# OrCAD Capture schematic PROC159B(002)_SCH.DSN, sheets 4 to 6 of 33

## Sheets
4 08. POWER INPUT: size C; title: USB-C POWER
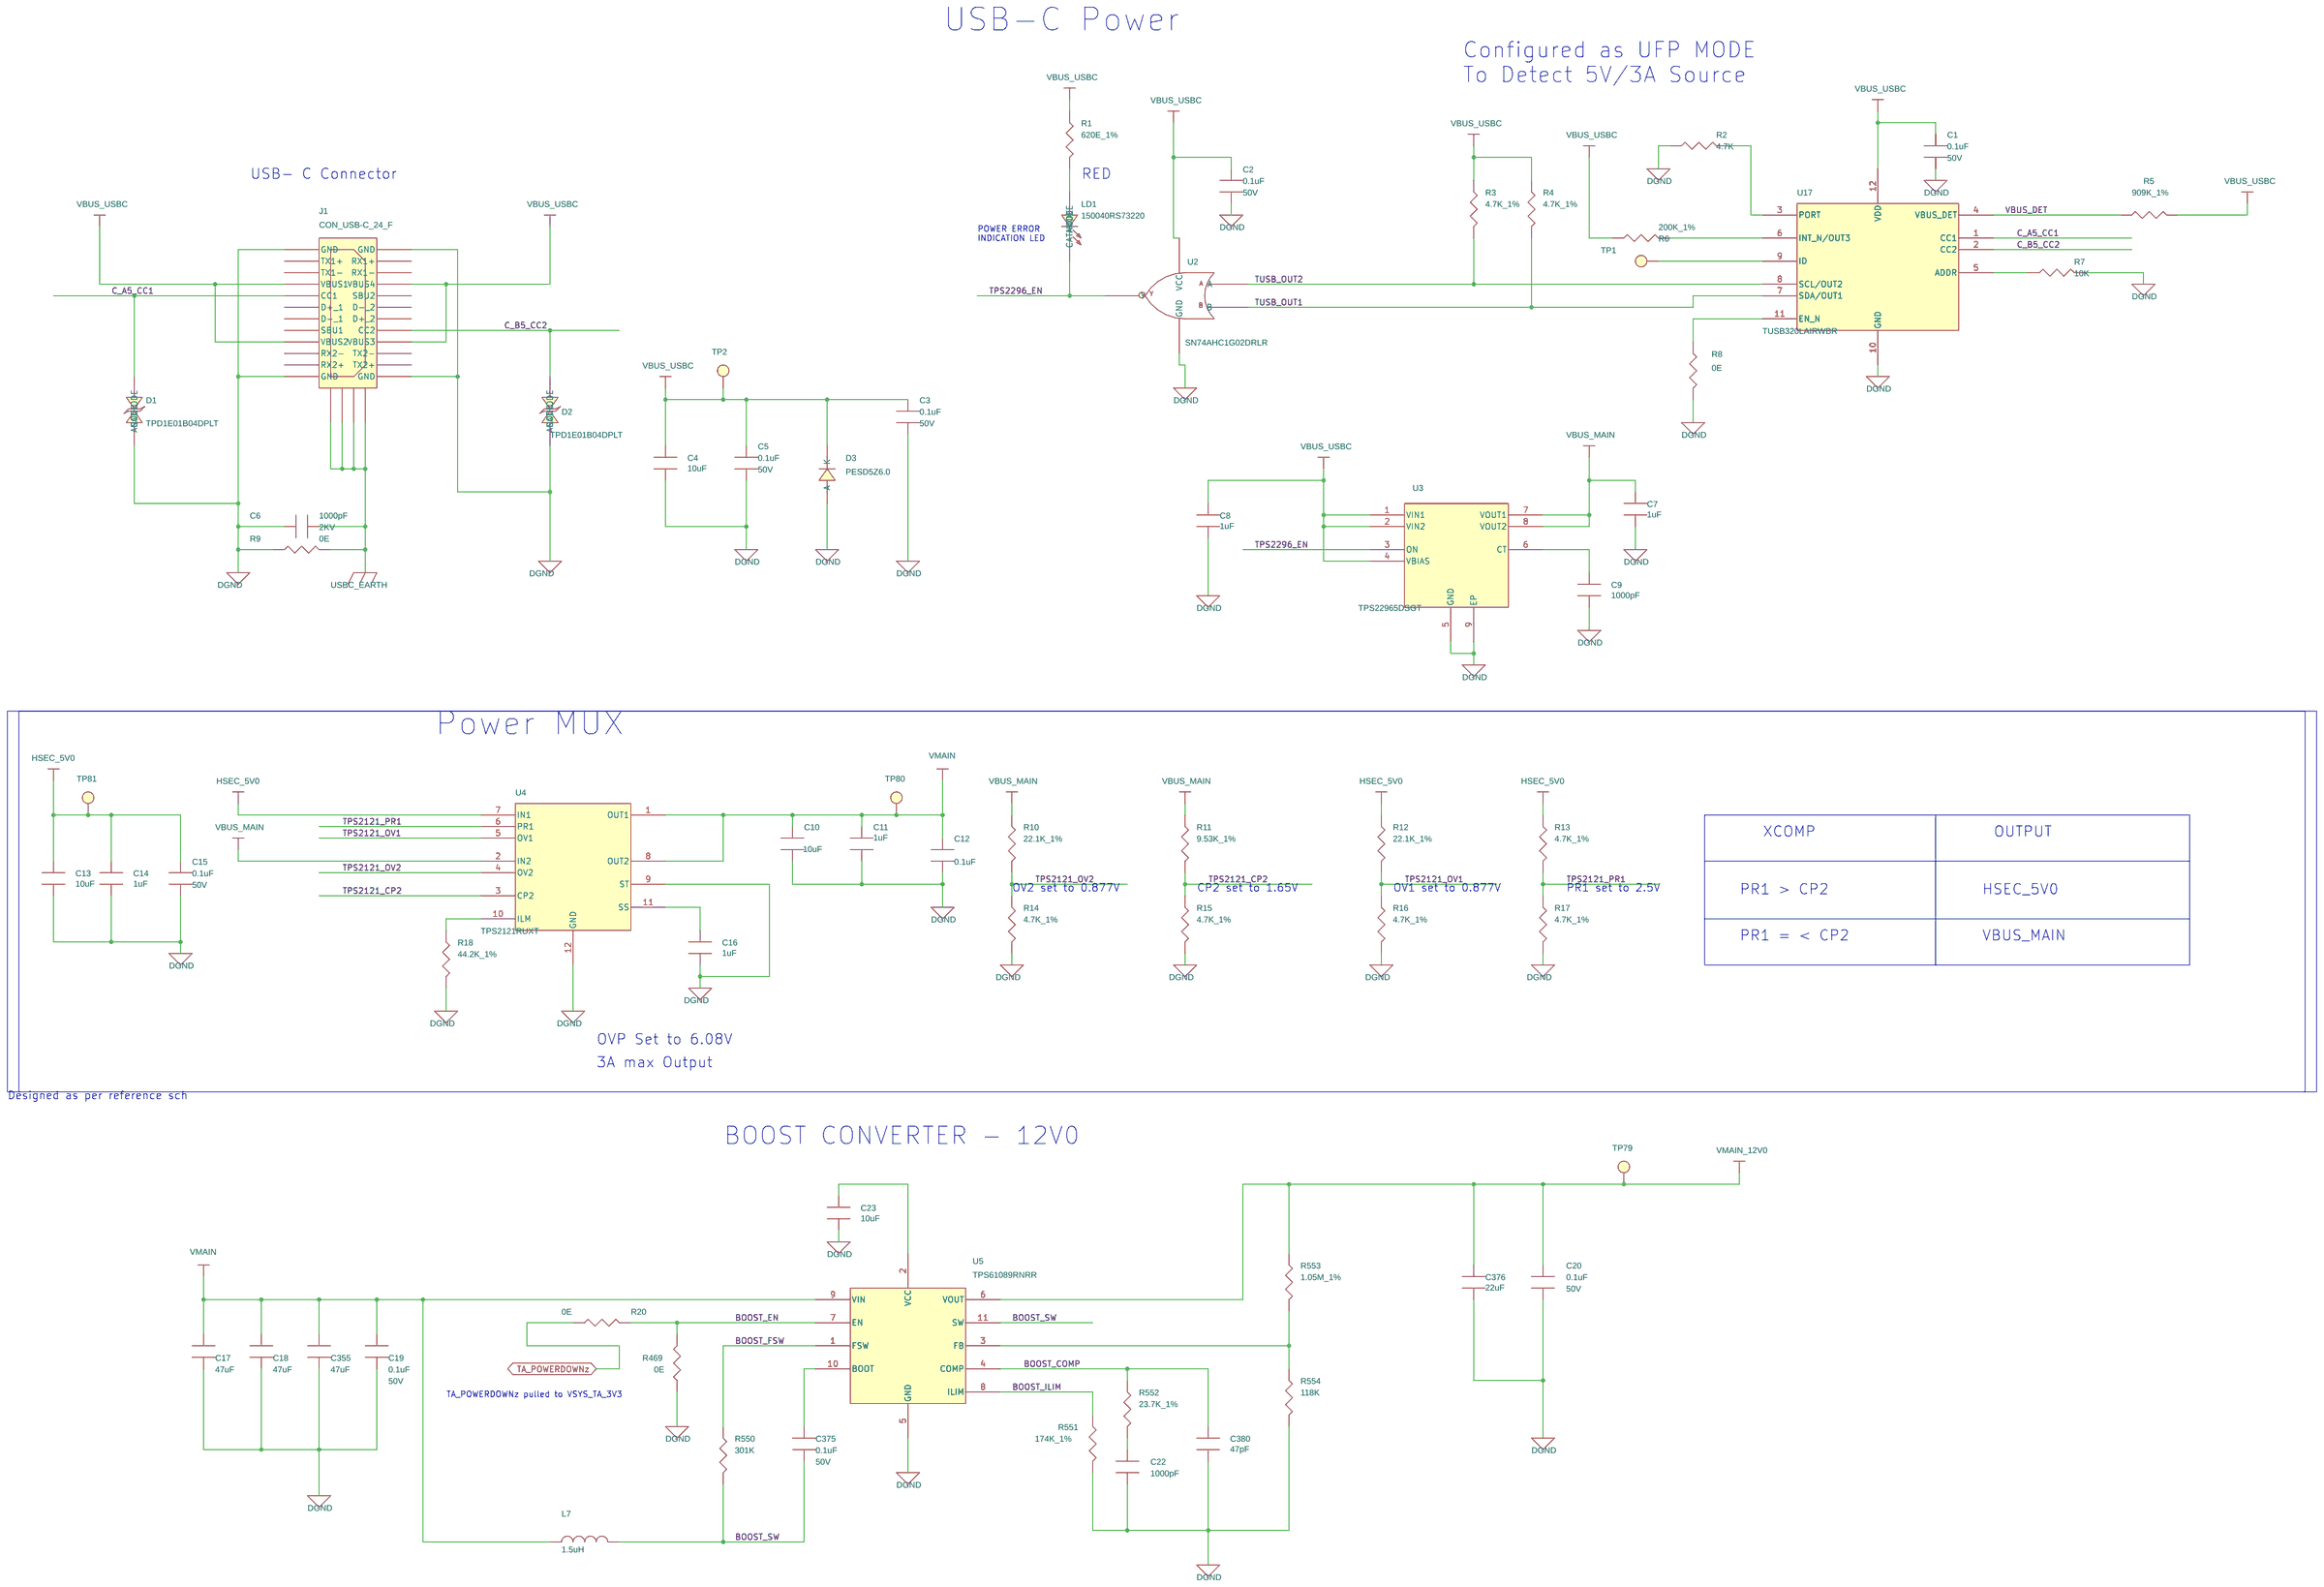
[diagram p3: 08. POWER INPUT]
5 04. POWER SEQUENCE: title: POWER SEQUENCE
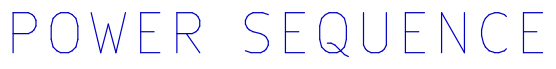
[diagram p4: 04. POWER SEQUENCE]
6 31. HSEC Connector: size C; title: HSEC CONN
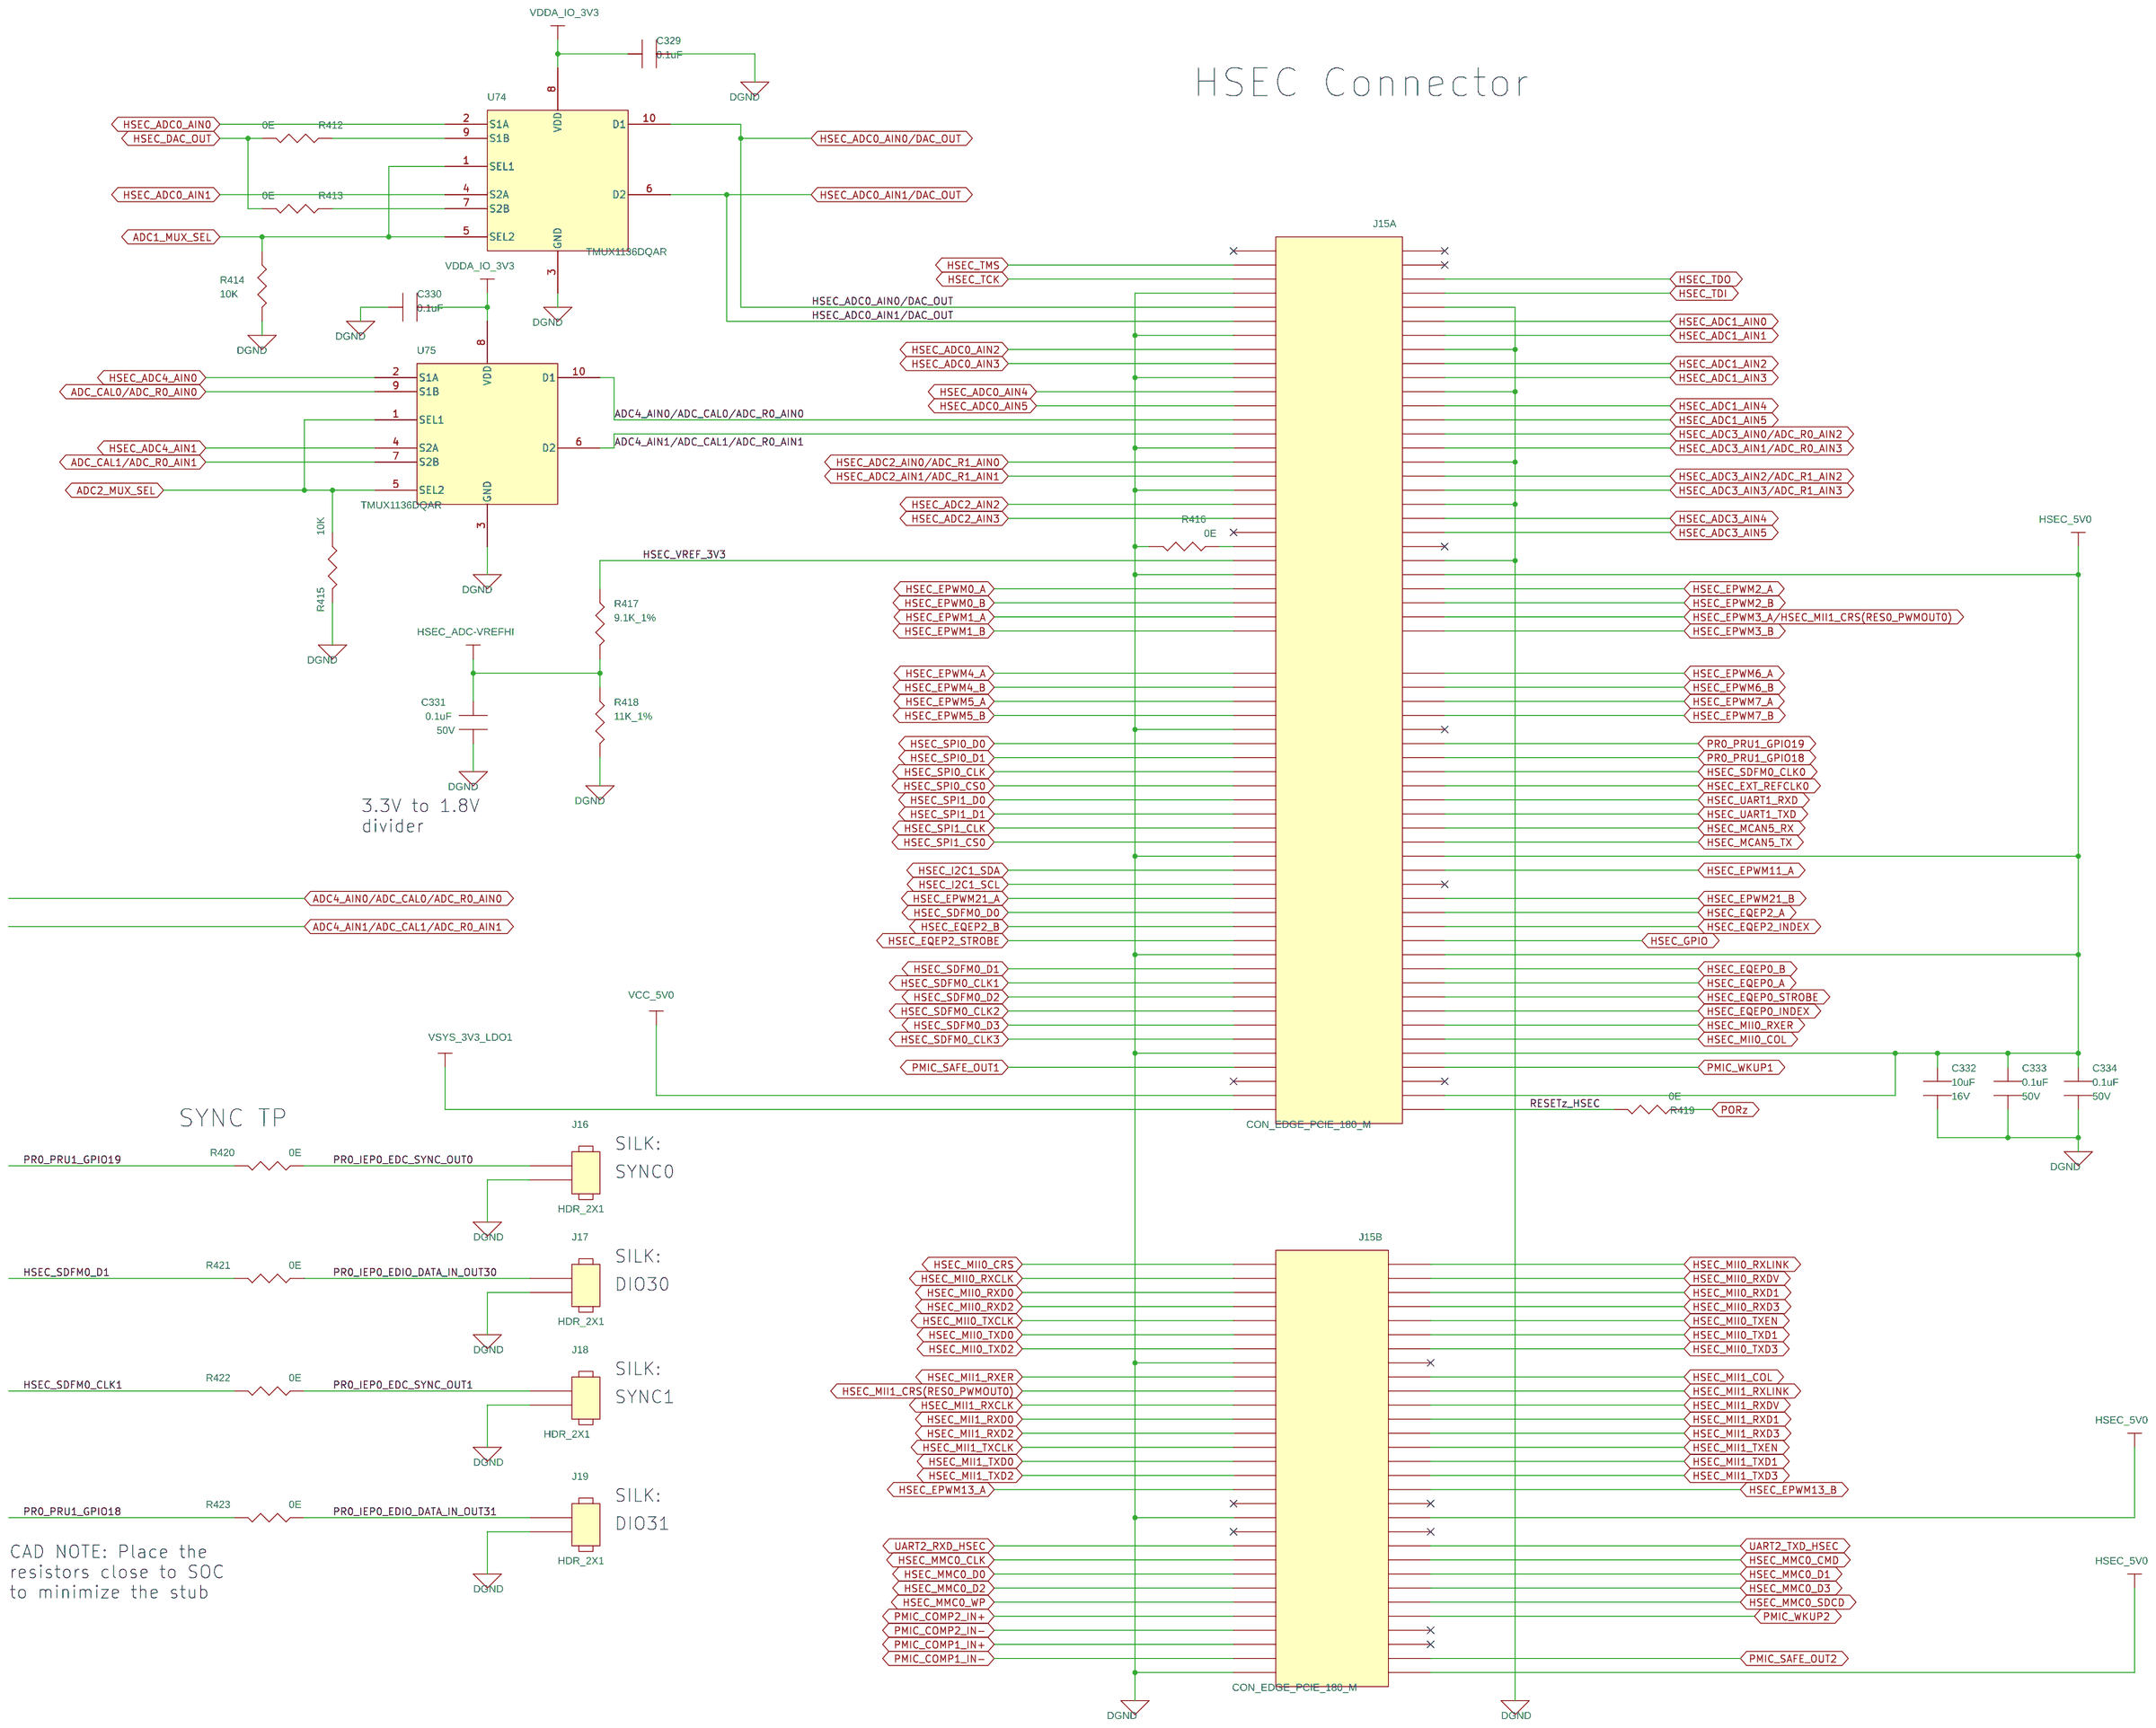
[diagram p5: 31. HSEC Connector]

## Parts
sheet 08. POWER INPUT
C1  0.1uF  [CAP0402_0-75]
C2  0.1uF  [CAP0402_0-75]
C3  0.1uF  [CAP0402_0-75]
C4  10uF  [CAP1206_2]
C5  0.1uF  [CAP0402_0-75]
C6  1000pF  [CAP1206_1-75]
C7  1uF  [CAP0402_0-75]
C8  1uF  [CAP0402_0-75]
C9  1000pF  [CAP0402_0-75]
C10  10uF  [CAP1206_2]
C11  1uF  [CAP0402_0-75]
C12  0.1uF  [CAP0402_0-75]
C13  10uF  [CAP1206_2]
C14  1uF  [CAP0402_0-75]
C15  0.1uF  [CAP0402_0-75]
C16  1uF  [CAP0402_0-75]
C17  47uF  [CAP1206_2]
C18  47uF  [CAP1206_2]
C19  0.1uF  [CAP0402_0-75]
C20  0.1uF  [CAP0402_0-75]
C22  1000pF  [CAP0402_0-75]
C23  10uF  [CAP0805_1-5]
C355  47uF  [CAP1206_2]
C375  0.1uF  [CAP0402_0-75]
C376  22uF  [CAP0805_1-5]
C380  47pF  [CAP0402_0-75]
D1  TPD1E01B04DPLT  [DIO_DFN0201_0-4]
D2  TPD1E01B04DPLT  [DIO_DFN0201_0-4]
D3  PESD5Z6.0  [DIO_SOD523F_0-7]
J1  CON_USB-C_24_F  [CON_USBC24_2012670_S_R_S_3-9]
L7  1.5uH  [IND1008]
LD1  150040RS73220  [LED_150040GS73220_40X20_SMD_0-4]
R1  620E_1%  [RES0402_0-5]
R2  4.7K  [RES0402_0-5]
R3  4.7K_1%  [RES0402_0-5]
R4  4.7K_1%  [RES0402_0-5]
R5  909K_1%  [RES0201_0-5]
R6  200K_1%  [RES0402_0-5]
R7  10K  [RES0402_0-5]
R8  0E  [RES0402_0-5]
R9  0E  [RES0805_0-75]
R10  22.1K_1%  [RES0402_0-5]
R11  9.53K_1%  [RES0402_0-5]
R12  22.1K_1%  [RES0402_0-5]
R13  4.7K_1%  [RES0402_0-5]
R14  4.7K_1%  [RES0402_0-5]
R15  4.7K_1%  [RES0402_0-5]
R16  4.7K_1%  [RES0402_0-5]
R17  4.7K_1%  [RES0402_0-5]
R18  44.2K_1%  [RES0402_0-5]
R20  0E  [RES0402_0-5]
R469  0E  [RES0402_0-5]
R550  301K  [RES0402_0-5]
R551  174K_1%  [RES0402_0-5]
R552  23.7K_1%  [RES0402_0-5]
R553  1.05M_1%  [RES0402_0-5]
R554  118K  [RES0402_0-5]
TP1  TP40_SMD  [TP40_SMD]
TP2  TP40_SMD  [TP40_SMD]
TP79  TP40_SMD  [TP40_SMD]
TP80  TP40_SMD  [TP40_SMD]
TP81  TP40_SMD  [TP40_SMD]
U2  SN74AHC1G02DRLR  [SOT553-5_0-6]
U3  TPS22965DSGT  [WSON8_19-68_80X80_0-8]
U4  TPS2121RUXT  [VQFNHR12_TPS2121_80X100_1]
U5  TPS61089RNRR  [VQFN11_TPS61089_100X80_1]
U17  TUSB320LAIRWBR  [X2QFN12_TUSB322I_60X60_0-4]
sheet 31. HSEC Connector
C329  0.1uF  [CAP0402_0-75]
C330  0.1uF  [CAP0402_0-75]
C331  0.1uF  [CAP0402_0-75]
C332  10uF  [CAP0603_1]
C333  0.1uF  [CAP0402_0-75]
C334  0.1uF  [CAP0402_0-75]
J15  CON_EDGE_PCIE_180_M  [CON_EDGE180_HSEC8-180_FING_P_R_S]  (sections A,B)
J16  HDR_2X1  [HDR_2X1_100_S_T_10-8]
J17  HDR_2X1  [HDR_2X1_100_S_T_10-8]
J18  HDR_2X1  [HDR_2X1_100_S_T_10-8]
J19  HDR_2X1  [HDR_2X1_100_S_T_10-8]
R412  0E  [RES0402_0-5]
R413  0E  [RES0402_0-5]
R414  10K  [RES0402_0-5]
R415  10K  [RES0402_0-5]
R416  0E  [RES0402_0-5]
R417  9.1K_1%  [RES0402_0-5]
R418  11K_1%  [RES0402_0-5]
R419  0E  [RES0402_0-5]
R420  0E  [RES0402_0-5]
R421  0E  [RES0402_0-5]
R422  0E  [RES0402_0-5]
R423  0E  [RES0402_0-5]
U74  TMUX1136DQAR  [USON10_TMUX1204_40X100_0-6]
U75  TMUX1136DQAR  [USON10_TMUX1204_40X100_0-6]

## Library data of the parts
C1-C3 C5 C15 C19 C20 C375 = CAP: CAP CERAMIC 0.1uF 50V 10% X7R 0402; Automotive Alternate_mfr_name: TDK; Automotive Alternate_mfr_part_number: CGA2B3X7R1H104K050BB; Chkd/date: MANIRAJA/261020; Crtd /date: ALVY/211020; Custom_Duty: 15%; Customs_HS_Code: 85322990; Direct Alternate_mfr_name: TDK; Direct Alternate_mfr_part_number: C1005X7R1H104K050BE; Distributor_name: DIGIKEY; Distributor_part_number: 490-10700-1-ND; Footprint Path: Y:\MIS_DATABASE\Library\ALTIUM_TOOL\PCB_FOOTPRINTS\Altium_Footprint_Lib.PcbLib; Height: 0.55MM; Library Path: Y:\MIS_DATABASE\Library\ALTIUM_TOOL\SCHEMATICS_PARTS\MS_DISCRETE_Library.schlib; Mfr_name: MURATA; Mfr_part_number: GRM155R71H104KE14D; Mistral Part No: 120011100014-R; Package: 0402; Part_type: CAPACITORS\CERAMIC; Project: J7_CP; RoHS: RoHS; Temperature: -55°C+125°C; Tolerance: 10%; Voltage: 50V; Wattage: NA; Weight: 3.1mg; Datasheet: Y:\MIS_DATABASE\DATASHEETS\CAPACITORS\GRM155R71H104KE14.PDF
C4 C10 C13 = CAP: CAP CERAMIC 10uF 50V 10% X7T 1206; Chkd/date: ALVY/010721; Crtd /date: MANIRAJA/010721; Custom_Duty: 15%; Customs_HS_Code: 85322990; Distributor_name: DIGIKEY; Distributor_part_number: 490-GRM31CD71H106KE11LCT-ND; Footprint Path: Y:\MIS_DATABASE\Library\ALTIUM_TOOL\PCB_FOOTPRINTS\Altium_Footprint_Lib.PcbLib; Height: 1.90MM; Library Path: Y:\MIS_DATABASE\Library\ALTIUM_TOOL\SCHEMATICS_PARTS\MS_DISCRETE_Library.schlib; Mfr_name: MURATA; Mfr_part_number: GRM31CD71H106KE11L; Mistral Part No: 120021070004-R; Package: 1206; Part_type: CAPACITORS\CERAMIC; Project: TI_AM263X_CC; RoHS: RoHS; Temperature: -55°C+125°C; Tolerance: 10%; Voltage: 50V; Wattage: NA; Weight: 27mg; Datasheet: Y:\MIS_DATABASE\DATASHEETS\CAPACITORS\GRM31CD71H106KE11.PDF
C6 = CAP: CAP CERAMIC 1000pF 2KV 10% X7R 1206; Automotive Alternate_mfr_name: KEMET; Automotive Alternate_mfr_part_number: C1206X102KGRACAUTO; Chkd/date: SHREESHAIL/291106; Crtd /date: MAZHAR/281106; Custom_Duty: 15%; Customs_HS_Code: 85322990; Direct Alternate_mfr_name: KEMET; Direct Alternate_mfr_part_number: C1206C102KGRACTU; Distributor_name: DIGIKEY; Distributor_part_number: 478-2956-1-ND; Footprint Path: Y:\MIS_DATABASE\Library\ALTIUM_TOOL\PCB_FOOTPRINTS\Altium_Footprint_Lib.PcbLib; Height: 1.52MM; Library Path: Y:\MIS_DATABASE\Library\ALTIUM_TOOL\SCHEMATICS_PARTS\MS_DISCRETE_Library.schlib; Mfr_name: AVX CORPORATION; Mfr_part_number: 1206GC102KAT1A; Mistral Part No: 120015080006-R; Package: 1206; Part_type: CAPACITORS\CERAMIC; Project: ADR1B; RoHS: RoHS; Temperature: -55°C+125°C; Tolerance: 10%; Voltage: 2KV; Wattage: NA; Weight: 16.2mg; Datasheet: Y:\MIS_DATABASE\DATASHEETS\CAPACITORS\AVX_HV-MLC.PDF
C7 C8 C11 C14 C16 = CAP: CAP CERAMIC 1uF 25V 10% X6S 0402; Chkd/date: MANIRAJA/140518; Crtd /date: ALVY/140518; Custom_Duty: 15%; Customs_HS_Code: 85322990; Distributor_name: DIGIKEY; Distributor_part_number: 490-10014-1-ND; Footprint Path: Y:\MIS_DATABASE\Library\ALTIUM_TOOL\PCB_FOOTPRINTS\Altium_Footprint_Lib.PcbLib; Height: 0.60MM; Library Path: Y:\MIS_DATABASE\Library\ALTIUM_TOOL\SCHEMATICS_PARTS\MS_DISCRETE_Library.schlib; Mfr_name: MURATA; Mfr_part_number: GRM155C81E105KE11D; Mistral Part No: 120018050004-R; Package: 0402; Part_type: CAPACITORS\CERAMIC; Project: TI_SVB_MAXWELL_DUT; RoHS: RoHS; Temperature: -55°C+105°C; Tolerance: 10%; Voltage: 25V; Wattage: NA; Weight: 6mg; Datasheet: Y:\MIS_DATABASE\DATASHEETS\CAPACITORS\GRM155C81E105KE11X.PDF
C9 C22 = CAP: CAP CERAMIC 1000pF 50V 5% C0G(NP0) 0402; Chkd/date: VASANTHA/281216; Crtd /date: MAZHAR/290806; Custom_Duty: 15%; Customs_HS_Code: 85322990; Distributor_name: DIGIKEY; Distributor_part_number: 490-3244-1-ND; Footprint Path: Y:\MIS_DATABASE\Library\ALTIUM_TOOL\PCB_FOOTPRINTS\Altium_Footprint_Lib.PcbLib; Height: 0.55MM; Library Path: Y:\MIS_DATABASE\Library\ALTIUM_TOOL\SCHEMATICS_PARTS\MS_DISCRETE_Library.schlib; Mfr_name: MURATA; Mfr_part_number: GRM1555C1H102JA01D; Mistral Part No: 120016110009-R; Package: 0402; Part_type: CAPACITORS\CERAMIC; Project: SVDO_RMB_MMA; RoHS: RoHS; Temperature: -55°C+125°C; Tolerance: 5%; Voltage: 50V; Wattage: NA; Weight: 6mg; Datasheet: Y:\MIS_DATABASE\DATASHEETS\CAPACITORS\MURATA-GXX-SER_NOV17.PDF
C12 = CAP: CAP CERAMIC 0.1uF 50V 10% X7R 0402; Alt_Mfr_name: YAGEO AMERICA; Alt_Mfr_part_number: CC0402KRX5R8BB104; Chkd/date: MANIRAJA/261020; Crtd /date: ALVY/211020; Custom_Duty: 15%; Customs_HS_Code: 85322990; Distributor_name: DIGIKEY; Distributor_part_number: 490-10700-1-ND; Footprint Path: Y:\MIS_DATABASE\Library\ALTIUM_TOOL\PCB_FOOTPRINTS\Altium_Footprint_Lib.PcbLib; Height: 0.55MM; Library Path: Y:\MIS_DATABASE\Library\ALTIUM_TOOL\SCHEMATICS_PARTS\MS_DISCRETE_Library.schlib; Mfr_name: MURATA; Mfr_part_number: GRM155R71H104KE14D; Mistral Part No: 120011100014-R; Package: 0402; Part_type: CAPACITORS\CERAMIC; Project: J7_CP; RoHS: RoHS; Temperature: -55°C+125°C; Tolerance: 10%; Voltage: 50V; Wattage: NA; Weight: 3.1mg; Datasheet: Y:\MIS_DATABASE\DATASHEETS\CAPACITORS\GRM155R71H104KE14.PDF
C17 C18 C355 = CAP: CAP CERAMIC 47uF 10V 20% X5R 1206; Chkd/date: USMAN/121213; Crtd /date: USMAN/121213; Custom_Duty: 15%; Customs_HS_Code: 85322990; Distributor_name: DIGIKEY; Distributor_part_number: 490-5528-1-ND; Footprint Path: Y:\MIS_DATABASE\Library\ALTIUM_TOOL\PCB_FOOTPRINTS\Altium_Footprint_Lib.PcbLib; Height: 1.80MM; Library Path: Y:\MIS_DATABASE\Library\ALTIUM_TOOL\SCHEMATICS_PARTS\MS_DISCRETE_Library.schlib; Mfr_name: MURATA; Mfr_part_number: GRM31CR61A476ME15L; Mistral Part No: 120013120015-R; Package: 1206; Part_type: CAPACITORS\CERAMIC; Project: DMP; RoHS: RoHS; Temperature: -55°C+85°C; Tolerance: 20%; Voltage: 10V; Wattage: NA; Weight: 40mg; Datasheet: Y:\MIS_DATABASE\DATASHEETS\CAPACITORS\MURATA-GXX-SER_NOV17.PDF
C23 = CAP: CAP CERAMIC 10uF 50V 10% X5R 0805; Chkd/date: MANIRAJA/010321; Crtd /date: ALVY/010321; Custom_Duty: 15%; Customs_HS_Code: 85322990; Distributor_name: DIGIKEY; Distributor_part_number: 490-18663-1-ND; Footprint Path: Y:\MIS_DATABASE\Library\ALTIUM_TOOL\PCB_FOOTPRINTS\Altium_Footprint_Lib.PcbLib; Height: 1.45MM; Library Path: Y:\MIS_DATABASE\Library\ALTIUM_TOOL\SCHEMATICS_PARTS\MS_DISCRETE_Library.schlib; Mfr_name: MURATA; Mfr_part_number: GRM21BR61H106KE43L; Mistral Part No: 120021030002-R; Package: 0805; Part_type: CAPACITORS\CERAMIC; Project: J7ES_SK_BRD; RoHS: RoHS; Temperature: -55°C+85°C; Tolerance: 10%; Voltage: 50V; Wattage: NA; Weight: 6.4mg; Datasheet: Y:\MIS_DATABASE\DATASHEETS\CAPACITORS\GRM21BR61H106KE43.PDF
C376 = CAP: CAP CERAMIC 22uF 25V 20% X5R 0805; Chkd/date: MANIRAJA/110718; Crtd /date: ALVY/110718; Custom_Duty: 15%; Customs_HS_Code: 85322990; Distributor_name: DIGIKEY; Distributor_part_number: 490-14661-1-ND; Footprint Path: Y:\MIS_DATABASE\Library\ALTIUM_TOOL\PCB_FOOTPRINTS\Altium_Footprint_Lib.PcbLib; Height: 1.45MM; Library Path: Y:\MIS_DATABASE\Library\ALTIUM_TOOL\SCHEMATICS_PARTS\MS_DISCRETE_Library.schlib; Mfr_name: MURATA; Mfr_part_number: GRM21BR61E226ME44K; Mistral Part No: 120013120018-R; Package: 0805; Part_type: CAPACITORS\CERAMIC; Project: TI_J7SVB_PCIE_ADD-ON-CARD; RoHS: RoHS; Temperature: -55°C+85°C; Tolerance: 20%; Voltage: 25V; Wattage: NA; Weight: 9.5mg; Datasheet: Y:\MIS_DATABASE\DATASHEETS\CAPACITORS\GRM21BR61E226ME44K.PDF
C380 = CAP: CAP CERAMIC 47pF 50V 5% C0G(NP0) 0402; Chkd/date: PRADEEP/040225; Crtd /date: SHANKARI/030225; Custom_Duty: 15%; Customs_HS_Code: 85322990; Distributor_name: DIGIKEY; Distributor_part_number: 490-14446-1-ND; Footprint Path: Y:\MIS_DATABASE\Library\ALTIUM_TOOL\PCB_FOOTPRINTS\Altium_Footprint_Lib.PcbLib; Height: 0.55MM; Library Path: Y:\MIS_DATABASE\Library\ALTIUM_TOOL\SCHEMATICS_PARTS\MS_DISCRETE_Library.schlib; Mfr_name: MURATA; Mfr_part_number: GJM1555C1H470JB01D; Mistral Part No: 120025020001-R; Package: 0402; Part_type: CAPACITORS\CERAMIC; Project: AM263P_CC_REV_B; RoHS: RoHS; Temperature: -55°C+125°C; Tolerance: 5%; Voltage: 50V; Wattage: NA; Weight: NA; Datasheet: Y:\MIS_DATABASE\DATASHEETS\CAPACITORS\GJM1555C1H470JB01D.PDF
D1 D2 = DIODE_TVS_DUAL: DIODE 1CH ESD PROTECTION FOR USB TYPE-C AND THUNDERBOLT3 X2SON2; Chkd/date: MANIRAJA/230920; Crtd /date: ALVY/230920; Custom_Duty: 15%; Customs_HS_Code: 85412900; Distributor_name: DIGIKEY; Distributor_part_number: 296-44484-1-ND; Footprint Path: Y:\MIS_DATABASE\Library\ALTIUM_TOOL\PCB_FOOTPRINTS\Altium_Footprint_Lib.PcbLib; Height: 0.32MM; Library Path: Y:\MIS_DATABASE\Library\ALTIUM_TOOL\SCHEMATICS_PARTS\MS_DISCRETE_Library.schlib; Mfr_name: TEXAS INSTRUMENTS; Mistral Part No: 130020090037-R; Package: X2SON2; Part_type: DIODE\TVS; Project: AM64X_SKEVM; RoHS: RoHS; Temperature: -40°C+125°C; Tolerance: NA; Voltage: NA; Wattage: NA; Weight: 0.2mg; Datasheet: Y:\MIS_DATABASE\DATASHEETS\DISCRETES\DIODES\TPD1E01B04.PDF
D3 = DIODE: DIODE 6V LOW CAPACITANCE UNIDIRECTIONAL ESD PROTECTION SOD523; Crtd /date: ALVY/230621; Custom_Duty: 15%; Customs_HS_Code: 85412900; Distributor_name: DIGIKEY; Distributor_part_number: 1727-5815-1-ND; Footprint Path: Y:\MIS_DATABASE\Library\ALTIUM_TOOL\PCB_FOOTPRINTS\Altium_Footprint_Lib.PcbLib; Height: 0.65MM; Library Path: Y:\MIS_DATABASE\Library\ALTIUM_TOOL\SCHEMATICS_PARTS\MS_DISCRETE_Library.schlib; Mfr_name: NEXPERIA; Mfr_part_number: PESD5Z6.0,115; Mistral Part No: 130021060065-R; Package: SOD523; Project: AM263x_CC; RoHS: RoHS; Temperature: -65°C+150°C; Tolerance: NA; Voltage: 6V; Wattage: NA; Weight: 1.49mg; Datasheet: Y:\MIS_DATABASE\DATASHEETS\DISCRETES\DIODES\PESD5ZX.PDF
J1 = CON_USB-C_24_1240183621: CON USB-C TYPE 24POS FEMALE RT SMD; Chkd/date: MANIRAJA/050618; Crtd /date: ALVY/040618; Custom_Duty: 24%; Customs_HS_Code: 85369090; Distributor_name: DIGIKEY; Distributor_part_number: WM17992CT-ND; Footprint Path: Y:\MIS_DATABASE\Library\ALTIUM_TOOL\PCB_FOOTPRINTS\Altium_Footprint_Lib.PcbLib; Height: 3.86MM; Library Path: Y:\MIS_DATABASE\Library\ALTIUM_TOOL\SCHEMATICS_PARTS\MS_CONNECTOR_Library.schlib; Mfr_name: MOLEX; Mfr_part_number: 2012670005; Mistral Part No: 150018060002-R; Package: SMD; Part_type: CONNECTOR\USB; Project: TI_J7SVB_USB_ADD-ON-CARD; RoHS: RoHS; Temperature: -40°C+105°C; Tolerance: NA; Voltage: NA; Wattage: NA; Weight: 0.686g; Datasheet: Y:\MIS_DATABASE\DATASHEETS\CONNECTORS\2012670X.PDF
L7 = INDUCTOR: IND 1.5uH 20% 3.5A 1008; Chkd/date: VASANTHA/280916; Crtd /date: VASANTHA/280916; Custom_Duty: 24%; Customs_HS_Code: 85437099; Distributor_name: DIGIKEY; Distributor_part_number: 490-10648-1-ND; Height: 1.20MM; Mfr_name: MURATA; Mfr_part_number: DFE252012P-1R5M=P2; Mistral Part No: 130016090011-R; Package: 1008; Project: GOLDEN-I LITE; RoHS: RoHS; Temperature: -40°C+125°C; Tolerance: 20%; Voltage: NA; Wattage: NA; Weight: NA; Datasheet: Y:\MIS_DATABASE\DATASHEETS\DISCRETES\INDUCTORS\DFE252012P.PDF
LD1 = DIODE_LED: DIODE LED RED SMD; Chkd/date: MANIRAJA/100920; Crtd /date: ALVY/100920; Custom_Duty: 24%; Customs_HS_Code: 85439000; Distributor_name: DIGIKEY; Distributor_part_number: 732-13422-1-ND; Footprint Path: Y:\MIS_DATABASE\Library\ALTIUM_TOOL\PCB_FOOTPRINTS\Altium_Footprint_Lib.PcbLib; Height: 0.35MM; Library Path: Y:\MIS_DATABASE\Library\ALTIUM_TOOL\SCHEMATICS_PARTS\MS_OPTO_Library.schlib; Mfr_name: WURTH ELECTRONICS; Mistral Part No: 130020090020-R; Package: SMD; Part_type: OPTO\LED; Project: AM64X_SKEVM; RoHS: RoHS; Temperature: -40°C+85°C; Tolerance: NA; Voltage: NA; Wattage: NA; Weight: 29.3mg; Datasheet: Y:\MIS_DATABASE\DATASHEETS\DISCRETES\LEDS\150040RS73220.PDF
R1 = RESISTOR: RES 620E 1/10W 1% 0402; Chkd/date: USMAN/120313; Crtd /date: CHAITHANYA/270912; Custom_Duty: 15%; Customs_HS_Code: 85332119; Distributor_name: DIGIKEY; Distributor_part_number: P620LCT-ND; Footprint Path: Y:\MIS_DATABASE\Library\ALTIUM_TOOL\PCB_FOOTPRINTS\Altium_Footprint_Lib.PcbLib; Height: 0.40MM; Library Path: Y:\MIS_DATABASE\Library\ALTIUM_TOOL\SCHEMATICS_PARTS\MS_DISCRETE_Library.schlib; Mfr_name: PANASONIC-ECG; Mfr_part_number: ERJ-2RKF6200X; Mistral Part No: 110012090013-R; Package: 0402; Part_type: RESISTORS\FIXED; Project: ITS-CONTROLER_CARD; RoHS: RoHS; Temperature: -55°C+155°C; Tolerance: 1%; Voltage: NA; Wattage: 1/10W; Weight: 0.8mg; Datasheet: Y:\MIS_DATABASE\DATASHEETS\RESISTORS\PAN-ERJSER_NOV17.PDF
R2 = RESISTOR: RES 4.7K 1/16W 5% 0402; Chkd/date: VASANTHA/130516; Crtd /date: VASANTHA/130516; Custom_Duty: 15%; Customs_HS_Code: 85332119; Distributor_name: DIGIKEY; Distributor_part_number: 311-4.7KJRCT-ND; Footprint Path: Y:\MIS_DATABASE\Library\ALTIUM_TOOL\PCB_FOOTPRINTS\Altium_Footprint_Lib.PcbLib; Height: 0.40MM; Library Path: Y:\MIS_DATABASE\Library\ALTIUM_TOOL\SCHEMATICS_PARTS\MS_DISCRETE_Library.schlib; Mfr_name: YAGEO AMERICA; Mfr_part_number: RC0402JR-074K7L; Mistral Part No: 110011060001-R; Package: 0402; Part_type: RESISTORS\FIXED; Project: TMDXCSK368; RoHS: RoHS; Temperature: -55°C+155°C; Tolerance: 5%; Voltage: NA; Wattage: 1/16W; Weight: 0.65mg; Datasheet: Y:\MIS_DATABASE\DATASHEETS\RESISTORS\RCXXXXL-SER_MAR18.PDF
R3 R4 R13-R17 = RESISTOR: RES 4.7K 1/16W 1% 0402; Chkd/date: VASANTHA/061216; Crtd /date: USMAN/070109; Custom_Duty: 15%; Customs_HS_Code: 85332119; Distributor_name: DIGIKEY; Distributor_part_number: 541-4.70KLCT-ND; Footprint Path: Y:\MIS_DATABASE\Library\ALTIUM_TOOL\PCB_FOOTPRINTS\Altium_Footprint_Lib.PcbLib; Height: 0.40MM; Library Path: Y:\MIS_DATABASE\Library\ALTIUM_TOOL\SCHEMATICS_PARTS\MS_DISCRETE_Library.schlib; Mfr_name: VISHAY; Mfr_part_number: CRCW04024K70FKED; Mistral Part No: 110009030797-R; Package: 0402; Part_type: RESISTORS\FIXED; Project: OMAP_EVM; RoHS: RoHS; Temperature: -55°C+155°C; Tolerance: 1%; Voltage: NA; Wattage: 1/16W; Weight: 0.65mg; Datasheet: Y:\MIS_DATABASE\DATASHEETS\RESISTORS\CRCW0603.PDF
R5 = RESISTOR: RES 909K 1/20W 1% 0201; Chkd/date: TAMILARASU/270423; Crtd /date: TAMILARASU/270423; Custom_Duty: 0.15; Customs_HS_Code: 85332119; Distributor_name: DIGIKEY; Distributor_part_number: P123197CT-ND; Footprint Path: Y:\MIS_DATABASE\Library\ALTIUM_TOOL\PCB_FOOTPRINTS\Altium_Footprint_Lib.PcbLib; Height: 0.26MM; Library Path: Y:\MIS_DATABASE\Library\ALTIUM_TOOL\SCHEMATICS_PARTS\MS_DISCRETE_Library.schlib; Mfr_name: PANASONIC-ECG; Mfr_part_number: ERJ-1GNF9093C; Mistral Part No: 110023040018-R; Package: 0201; Part_type: RESISTORS\FIXED; Project: AM263P_CC; RoHS: RoHS; Temperature: -55°C+125°C; Tolerance: 1%; Voltage: NA; Wattage: 1/20W; Weight: 0.15mg; Datasheet: Y:\MIS_DATABASE\DATASHEETS\RESISTORS\PAN-ERJSER_NOV17.PDF
R6 = RESISTOR: RES 200K 1/10W 1% 0402; Chkd/date: SHREESHAIL/121205; Crtd /date: MAZHAR/010805; Custom_Duty: 15%; Customs_HS_Code: 85332119; Distributor_name: DIGIKEY; Distributor_part_number: P200KLCT-ND; Footprint Path: Y:\MIS_DATABASE\Library\ALTIUM_TOOL\PCB_FOOTPRINTS\Altium_Footprint_Lib.PcbLib; Height: 0.40MM; Library Path: Y:\MIS_DATABASE\Library\ALTIUM_TOOL\SCHEMATICS_PARTS\MS_DISCRETE_Library.schlib; Mfr_name: PANASONIC-ECG; Mfr_part_number: ERJ-2RKF2003X; Mistral Part No: 110009030474-R; Package: 0402; Part_type: RESISTORS\FIXED; Project: PMP-VIOMEDIA; RoHS: RoHS; Temperature: -55°C+155°C; Tolerance: 1%; Voltage: NA; Wattage: 1/10W; Weight: 0.8mg; Datasheet: Y:\MIS_DATABASE\DATASHEETS\RESISTORS\PAN-ERJSER_NOV17.PDF
R7 R414 R415 = RESISTOR: RES 10K 1/16W 5% 0402; Chkd/date: VASANTHA/061216; Crtd /date: MAZHAR/230805; Custom_Duty: 15%; Customs_HS_Code: 85332119; Distributor_name: DIGIKEY; Distributor_part_number: 311-10KJRCT-ND; Footprint Path: Y:\MIS_DATABASE\Library\ALTIUM_TOOL\PCB_FOOTPRINTS\Altium_Footprint_Lib.PcbLib; Height: 0.40MM; Library Path: Y:\MIS_DATABASE\Library\ALTIUM_TOOL\SCHEMATICS_PARTS\MS_DISCRETE_Library.schlib; Mfr_name: YAGEO AMERICA; Mfr_part_number: RC0402JR-0710KL; Mistral Part No: 110011060021-R; Package: 0402; Part_type: RESISTORS\FIXED; Project: HSE; RoHS: RoHS; Temperature: -55°C+155°C; Tolerance: 5%; Voltage: NA; Wattage: 1/16W; Weight: 0.65mg; Datasheet: Y:\MIS_DATABASE\DATASHEETS\RESISTORS\RCXXXXL-SER_MAR18.PDF
R8 R20 R412 R413 R416 R419-R423 R469 = RESISTOR: RES 0E 1/10W JUMPER 0402; Chkd/date: VASANTHA/061216; Crtd /date: NAVEED/201014; Custom_Duty: 15%; Customs_HS_Code: 85332119; Distributor_name: DIGIKEY; Distributor_part_number: P0.0JCT-ND; Footprint Path: Y:\MIS_DATABASE\Library\ALTIUM_TOOL\PCB_FOOTPRINTS\Altium_Footprint_Lib.PcbLib; Height: 0.40MM; IBISSP_MODLES: VALUE REPEATING 2 TIME; Library Path: Y:\MIS_DATABASE\Library\ALTIUM_TOOL\SCHEMATICS_PARTS\MS_DISCRETE_Library.schlib; Mfr_name: PANASONIC-ECG; Mfr_part_number: ERJ-2GE0R00X; Mistral Part No: 110018030052-R; Package: 0402; Part_type: RESISTORS\FIXED; Project: AEGIS POM; RoHS: RoHS; Temperature: -55°C+155°C; Tolerance: NA; Voltage: NA; Wattage: 1/10W; Weight: 0.8mg; Datasheet: Y:\MIS_DATABASE\DATASHEETS\RESISTORS\PAN-ERJSER_NOV17.PDF
R9 = RESISTOR: RES 0E 1/8W 5% 0805; Chkd/date: VASANTHA/130416; Crtd /date: JEBRAN/020316; Custom_Duty: 15%; Customs_HS_Code: 85332119; Distributor_name: DIGIKEY; Distributor_part_number: 311-0.0ARCT-ND; Footprint Path: Y:\MIS_DATABASE\Library\ALTIUM_TOOL\PCB_FOOTPRINTS\Altium_Footprint_Lib.PcbLib; Height: 0.60MM; Library Path: Y:\MIS_DATABASE\Library\ALTIUM_TOOL\SCHEMATICS_PARTS\MS_DISCRETE_Library.schlib; Mfr_name: YAGEO AMERICA; Mfr_part_number: RC0805JR-070RL; Mistral Part No: 110009030074-R; Package: 0805; Part_type: RESISTORS\FIXED; Project: ZK_BIOMETRIC; RoHS: RoHS; Temperature: -55°C+155°C; Tolerance: 5%; Voltage: NA; Wattage: 1/8W; Weight: 5.5mg; Datasheet: Y:\MIS_DATABASE\DATASHEETS\RESISTORS\RCXXXXL-SER_MAR18.PDF
R10 R12 = RESISTOR: RES 22.1K 1/16W 1% 0402; Chkd/date: MAZHAR/101110; Crtd /date: BAVISH/091110; Custom_Duty: 15%; Customs_HS_Code: 85332119; Distributor_name: DIGIKEY; Distributor_part_number: 541-22.1KLCT-ND; Footprint Path: Y:\MIS_DATABASE\Library\ALTIUM_TOOL\PCB_FOOTPRINTS\Altium_Footprint_Lib.PcbLib; Height: 0.40MM; Library Path: Y:\MIS_DATABASE\Library\ALTIUM_TOOL\SCHEMATICS_PARTS\MS_DISCRETE_Library.schlib; Mfr_name: VISHAY; Mfr_part_number: CRCW040222K1FKED; Mistral Part No: 110010110004-R; Package: 0402; Part_type: RESISTORS\FIXED; Project: CPCI3GADC_CARD; RoHS: RoHS; Temperature: -55°C+155°C; Tolerance: 1%; Voltage: NA; Wattage: 1/16W; Weight: 0.65mg; Datasheet: Y:\MIS_DATABASE\DATASHEETS\RESISTORS\CRCW0603.PDF
R11 = RESISTOR: RES 9.53K 1/16W 1% 0402; Chkd/date: MANIRAJA/070521; Crtd /date: ALVY/070521; Custom_Duty: 15%; Customs_HS_Code: 85332119; Distributor_name: DIGIKEY; Distributor_part_number: 311-9.53KLRCT-ND; Footprint Path: Y:\MIS_DATABASE\Library\ALTIUM_TOOL\PCB_FOOTPRINTS\Altium_Footprint_Lib.PcbLib; Height: 0.40MM; Library Path: Y:\MIS_DATABASE\Library\ALTIUM_TOOL\SCHEMATICS_PARTS\MS_DISCRETE_Library.schlib; Mfr_name: YAGEO AMERICA; Mfr_part_number: RC0402FR-079K53L; Mistral Part No: 110021050001-R; Package: 0402; Part_type: RESISTORS\FIXED; Project: TI_AM263X_SVB_DUT; RoHS: RoHS; Temperature: -55°C+155°C; Tolerance: 1%; Voltage: NA; Wattage: 1/16W; Weight: 0.65mg; Datasheet: Y:\MIS_DATABASE\DATASHEETS\RESISTORS\RCXXXXL-SER_MAR18.PDF
R18 = RESISTOR: RES 44.2K 1/10W 1% 0402; Chkd/date: MAZHAR/041208; Crtd /date: USMAN/181108; Custom_Duty: 15%; Customs_HS_Code: 85332119; Distributor_name: DIGIKEY; Distributor_part_number: P44.2KLCT-ND; Footprint Path: Y:\MIS_DATABASE\Library\ALTIUM_TOOL\PCB_FOOTPRINTS\Altium_Footprint_Lib.PcbLib; Height: 0.40MM; Library Path: Y:\MIS_DATABASE\Library\ALTIUM_TOOL\SCHEMATICS_PARTS\MS_DISCRETE_Library.schlib; Mfr_name: PANASONIC-ECG; Mfr_part_number: ERJ-2RKF4422X; Mistral Part No: 110009030845-R; Package: 0402; Part_type: RESISTORS\FIXED; Project: PICO PROJECTOR; RoHS: RoHS; Temperature: -55°C+155°C; Tolerance: 1%; Voltage: NA; Wattage: 1/10W; Weight: 0.8mg; Datasheet: Y:\MIS_DATABASE\DATASHEETS\RESISTORS\PAN-ERJSER_NOV17.PDF
R550 = RESISTOR: RES 301K 1/16W 1% 0402; Crtd /date: SHANKARI/030225; Custom_Duty: 15%; Customs_HS_Code: 85332119; Distributor_name: DIGIKEY; Distributor_part_number: 541-301KLCT-ND; Footprint Path: Y:\MIS_DATABASE\Library\ALTIUM_TOOL\PCB_FOOTPRINTS\Altium_Footprint_Lib.PcbLib; Height: 0.40MM; Library Path: Y:\MIS_DATABASE\Library\ALTIUM_TOOL\SCHEMATICS_PARTS\MS_DISCRETE_Library.schlib; Mfr_name: VISHAY; Mfr_part_number: CRCW0402301KFKED; Mistral Part No: 110025020001-R; Package: 0402; Part_type: RESISTORS\FIXED; Project: AM263P_CC_REV_B; RoHS: RoHS; Temperature: -55°C+155°C; Tolerance: 0.01; Voltage: NA; Wattage: 1/16W; Weight: NA; Datasheet: Y:\MIS_DATABASE\DATASHEETS\RESISTORS\CRCW0402301KFKED3.PDF
R551 = RESISTOR: RES 174K 1/16W 1% 0402; Chkd/date: MANIRAJA/040619; Crtd /date: ALVY/030619; Custom_Duty: 15%; Customs_HS_Code: 85332119; Distributor_name: DIGIKEY; Distributor_part_number: 541-174KLCT-ND; Footprint Path: Y:\MIS_DATABASE\Library\ALTIUM_TOOL\PCB_FOOTPRINTS\Altium_Footprint_Lib.PcbLib; Height: 0.40MM; Library Path: Y:\MIS_DATABASE\Library\ALTIUM_TOOL\SCHEMATICS_PARTS\MS_DISCRETE_Library.schlib; Mfr_name: VISHAY; Mfr_part_number: CRCW0402174KFKED; Mistral Part No: 110019040290-R; Package: 0402; Part_type: RESISTORS\FIXED; Project: MYTHIC_FORMFACTOR_BRD; RoHS: RoHS; Temperature: -55°C+155°C; Tolerance: 1%; Voltage: NA; Wattage: 1/16W; Weight: 0.65mg; Datasheet: Y:\MIS_DATABASE\DATASHEETS\RESISTORS\CRCW0603.PDF
R552 = RESISTOR: RES 23.7K 1/16W 1% 0402; Chkd/date: MAZHAR/280809; Crtd /date: MAZHAR/280809; Custom_Duty: 15%; Customs_HS_Code: 85332119; Distributor_name: MOUSER; Distributor_part_number: 71-CRCW0402-23.7K-E3; Footprint Path: Y:\MIS_DATABASE\Library\ALTIUM_TOOL\PCB_FOOTPRINTS\Altium_Footprint_Lib.PcbLib; Height: 0.40MM; Library Path: Y:\MIS_DATABASE\Library\ALTIUM_TOOL\SCHEMATICS_PARTS\MS_DISCRETE_Library.schlib; Mfr_name: VISHAY; Mfr_part_number: CRCW040223K7FKED; Mistral Part No: 110009080029-R; Package: 0402; Part_type: RESISTORS\FIXED; Project: GOLDEN-I; RoHS: RoHS; Temperature: -55°C+155°C; Tolerance: 1%; Voltage: NA; Wattage: 1/16W; Weight: 0.65mg; Datasheet: Y:\MIS_DATABASE\DATASHEETS\RESISTORS\CRCW0603.PDF
R553 = RESISTOR: RES 1.05M 1/16W 1% 0402; Chkd/date: MANIRAJA/260320; Crtd /date: ALVY/240320; Custom_Duty: 15%; Customs_HS_Code: 85332119; Distributor_name: DIGIKEY; Distributor_part_number: 541-1.05MLCT-ND; Footprint Path: Y:\MIS_DATABASE\Library\ALTIUM_TOOL\PCB_FOOTPRINTS\Altium_Footprint_Lib.PcbLib; Height: 0.40MM; Library Path: Y:\MIS_DATABASE\Library\ALTIUM_TOOL\SCHEMATICS_PARTS\MS_DISCRETE_Library.schlib; Mfr_name: VISHAY; Mfr_part_number: CRCW04021M05FKED; Mistral Part No: 110020030033-R; Package: 0402; Part_type: RESISTORS\FIXED; Project: DARE_ECU_MCB; RoHS: RoHS; Temperature: -55°C+155°C; Tolerance: 1%; Voltage: NA; Wattage: 1/16W; Weight: 0.65mg; Datasheet: Y:\MIS_DATABASE\DATASHEETS\RESISTORS\CRCW0603.PDF
R554 = RESISTOR: RES 118K 1/16W 1% 0402; Crtd /date: SHANKARI/030225; Custom_Duty: 0.15; Customs_HS_Code: 85332119; Distributor_name: DIGIKEY; Distributor_part_number: 541-118KLCT-ND; Footprint Path: Y:\MIS_DATABASE\Library\ALTIUM_TOOL\PCB_FOOTPRINTS\Altium_Footprint_Lib.PcbLib; Height: 0.40MM; Library Path: Y:\MIS_DATABASE\Library\ALTIUM_TOOL\SCHEMATICS_PARTS\MS_DISCRETE_Library.schlib; Mfr_name: VISHAY; Mfr_part_number: CRCW0402118KFKED; Mistral Part No: 110025020002-R; Package: 0402; Part_type: RESISTORS\FIXED; Project: AM263P_CC_REV_B; RoHS: RoHS; Temperature: -55°C+155°C; Tolerance: 0.01; Voltage: NA; Wattage: 1/16W; Weight: NA; Datasheet: Y:\MIS_DATABASE\DATASHEETS\RESISTORS\CRCW0402118KFKED.PDF
TP1 TP2 TP79-TP81 = TESTPOINT: TESTPOINT CIR 40 SMD; Chkd/date: MAZHAR/190505; Crtd /date: MAZHAR/190505; Distributor_name: NA; Distributor_part_number: NA; Footprint Path: Y:\MIS_DATABASE\Library\ALTIUM_TOOL\PCB_FOOTPRINTS\Altium_Footprint_Lib.PcbLib; Height: NA; Library Path: Y:\MIS_DATABASE\Library\ALTIUM_TOOL\SCHEMATICS_PARTS\MS_DISCRETE_Library.schlib; MECHANICAL 3D STEP FILE: NA; Mfr_name: LOCAL; Mistral Part No: 130009030933; Package: SMD; Project: RAINIER-3; RoHS: NA; Temperature: NA; Tolerance: NA; Voltage: NA; Wattage: NA; Weight: NA; Datasheet: NA
U2 = SN74AHC1G02DBV_SOT23-5: IC SINGLE 2-INPUT POSITIVE-NOR GATE SOT553-5; Chkd/date: MANIRAJA/141020; Crtd /date: ALVY/131020; Custom_Duty: 15%; Customs_HS_Code: 85423100; Distributor_name: DIGIKEY; Distributor_part_number: 296-23229-1-ND; Footprint Path: Y:\MIS_DATABASE\Library\ALTIUM_TOOL\PCB_FOOTPRINTS\Altium_Footprint_Lib.PcbLib; Height: 0.60MM; Library Path: Y:\MIS_DATABASE\Library\ALTIUM_TOOL\SCHEMATICS_PARTS\MS_GATE_Library.schlib; Mfr_name: TEXAS INSTRUMENTS; Mistral Part No: 141020100014-R; Package: SOT553-5; Part_type: ICS\DIGITAL\GATES; Project: AM64X_SKEVM; RoHS: RoHS; Temperature: -40°C+125°C; Tolerance: NA; Voltage: NA; Wattage: NA; Weight: 2.8mg; Datasheet: Y:\MIS_DATABASE\DATASHEETS\ICS\DIGITAL\GATES\SN74AHC1G02XX.PDF
U3 = TPS22965DSGT_WSON8: IC 5.7V 6A 1-CHANNEL 16mE ON-RESISTANCE LOAD SWITCH WSON8; Chkd/date: MANIRAJA/080817; Crtd /date: VASANTHA/280714; Custom_Duty: 15%; Customs_HS_Code: 85423100; Distributor_name: DIGIKEY; Distributor_part_number: 296-34943-1-ND; Footprint Path: Y:\MIS_DATABASE\Library\ALTIUM_TOOL\PCB_FOOTPRINTS\Altium_Footprint_Lib.PcbLib; Height: 0.80MM; Library Path: Y:\MIS_DATABASE\Library\ALTIUM_TOOL\SCHEMATICS_PARTS\MS_MISCPOWER_Library.schlib; Mfr_name: TEXAS INSTRUMENTS; Mistral Part No: 142014070020-R; Package: WSON8; Part_type: ICS\POWER\DRIVER; Project: DC_MIST_DIGITAL CARD; RoHS: RoHS; Temperature: -40°C+105°C; Tolerance: NA; Voltage: NA; Wattage: NA; Weight: 11mg; Datasheet: Y:\MIS_DATABASE\DATASHEETS\ICS\POWER\TPS22965-SER.PDF
U4 = TPS2121RUXT_VQFNHR12: IC 4.5A 56mE PRIORITY POWER MUX WITH SEAMLESS SWITCHOVER VQFN-HR12; Chkd/date: VASANTHA/270319; Crtd /date: ALVY/270319; Custom_Duty: 15%; Customs_HS_Code: 85423100; Distributor_name: DIGIKEY; Distributor_part_number: 296-53412-1-ND; Footprint Path: Y:\MIS_DATABASE\Library\ALTIUM_TOOL\PCB_FOOTPRINTS\Altium_Footprint_Lib.PcbLib; Height: 1.00MM; Library Path: Y:\MIS_DATABASE\Library\ALTIUM_TOOL\SCHEMATICS_PARTS\MS_MISCPOWER_Library.schlib; Mfr_name: TEXAS INSTRUMENTS; Mistral Part No: 142019030004-R; Package: VQFN-HR12; Part_type: ICS\POWER; Project: RFSU BACKPLANE; RoHS: RoHS; Temperature: -40°C+125°C; Tolerance: NA; Voltage: NA; Wattage: NA; Weight: NA; Datasheet: Y:\MIS_DATABASE\DATASHEETS\ICS\POWER\TPS212XX.PDF
U5 = TPS61089_VQFN11: IC 12.6V 7A FULLY INTEGRATED SYNCHRONOUS BOOST CONVERTERS VQFN11; Chkd/date: PRADEEP/091224; Crtd /date: SHANKARI/091224; Custom_Duty: 0.24; Customs_HS_Code: 85369090; Distributor_name: DIGIKEY; Distributor_part_number: 296-47295-1-ND; Footprint Path: Y:\MIS_DATABASE\Library\ALTIUM_TOOL\PCB_FOOTPRINTS\Altium_Footprint_Lib.PcbLib; Height: 1.00MM; Library Path: Y:\MIS_DATABASE\Library\ALTIUM_TOOL\SCHEMATICS_PARTS\MS_MISCPOWER_Library.schlib; Mfr_name: TEXAS INSTRUMENTS; Mistral Part No: 142024120003-R; Package: VQFN11; Part_type: ICS\POWER\MANAGEMENT; Project: KIDKO; RoHS: RoHS; Temperature: -40°C+125°C; Tolerance: NA; Voltage: NA; Wattage: NA; Weight: NA; Datasheet: Y:\MIS_DATABASE\DATASHEETS\ICS\POWER\TPS61089RNRR.PDF
U17 = TUSB320LAI_X2QFN12: IC USB TYPE-C CHANNEL LOGIC AND PORT CONTROL X2QFN12; Chkd/date: MANIRAJA/210920; Crtd /date: ALVY/210920; Custom_Duty: 15%; Customs_HS_Code: 85423100; Distributor_name: DIGIKEY; Distributor_part_number: 296-TUSB320LAIRWBRCT-ND; Footprint Path: Y:\MIS_DATABASE\Library\ALTIUM_TOOL\PCB_FOOTPRINTS\Altium_Footprint_Lib.PcbLib; Height: 0.40MM; Library Path: Y:\MIS_DATABASE\Library\ALTIUM_TOOL\SCHEMATICS_PARTS\MS_MISCINTERFACE_Library.schlib; Mfr_name: TEXAS INSTRUMENTS; Mistral Part No: 141020090030-R; Package: X2QFN12; Part_type: ICS\INTERFACE; Project: AM64X_SKEVM; RoHS: RoHS; Temperature: -40°C+85°C; Tolerance: NA; Voltage: NA; Wattage: NA; Weight: 5mg; Datasheet: Y:\MIS_DATABASE\DATASHEETS\ICS\INTERFACE\TUSB320LAI.PDF
C329-C331 C333 C334 = CAP: CAP CERAMIC 0.1uF 50V 10% X7R 0402; Chkd/date: MANIRAJA/261020; Crtd /date: ALVY/211020; Custom_Duty: 15%; Customs_HS_Code: 85322990; Distributor_name: DIGIKEY; Distributor_part_number: 490-10700-1-ND; Footprint Path: Y:\MIS_DATABASE\Library\ALTIUM_TOOL\PCB_FOOTPRINTS\Altium_Footprint_Lib.PcbLib; Height: 0.55MM; Library Path: Y:\MIS_DATABASE\Library\ALTIUM_TOOL\SCHEMATICS_PARTS\MS_DISCRETE_Library.schlib; Mfr_name: MURATA; Mfr_part_number: GRM155R71H104KE14D; Mistral Part No: 120011100014-R; Package: 0402; Part_type: CAPACITORS\CERAMIC; Project: J7_CP; RoHS: RoHS; Temperature: -55°C+125°C; Tolerance: 10%; Voltage: 50V; Wattage: NA; Weight: 3.1mg; Datasheet: Y:\MIS_DATABASE\DATASHEETS\CAPACITORS\GRM155R71H104KE14.PDF
C332 = CAP: CAP CERAMIC 10uF 16V 20% X6S 0603; Chkd/date: VASANTHA/170117; Crtd /date: VASANTHA/170117; Custom_Duty: 15%; Customs_HS_Code: 85322990; Distributor_name: DIGIKEY; Distributor_part_number: 490-7198-1-ND; Footprint Path: Y:\MIS_DATABASE\Library\ALTIUM_TOOL\PCB_FOOTPRINTS\Altium_Footprint_Lib.PcbLib; Height: 0.90MM; Library Path: Y:\MIS_DATABASE\Library\ALTIUM_TOOL\SCHEMATICS_PARTS\MS_DISCRETE_Library.schlib; Mfr_name: MURATA; Mfr_part_number: GRM188C81C106MA73D; Mistral Part No: 120017010004-R; Package: 0603; Part_type: CAPACITORS\CERAMIC; Project: TRMM_SMART-M_PS; RoHS: RoHS; Temperature: -55°C+105°C; Tolerance: 20%; Voltage: 16V; Wattage: NA; Weight: 6.3mg; Datasheet: Y:\MIS_DATABASE\DATASHEETS\CAPACITORS\MURATA-GXX-SER_NOV17.PDF
J15 = CON_EDGE_180_HSEC8-180: CON EDGE PCIE FINGERS 180POS 0.80MM PITCH MALE RT SMD; Chkd/date: ALVY/250321; Crtd /date: MANIRAJA/250321; Custom_Duty: NA; Customs_HS_Code: NA; Distributor_name: NA; Distributor_part_number: NA; Footprint Path: Y:\MIS_DATABASE\Library\ALTIUM_TOOL\PCB_FOOTPRINTS\Altium_Footprint_Lib.PcbLib; Height: NA; Library Path: Y:\MIS_DATABASE\Library\ALTIUM_TOOL\SCHEMATICS_PARTS\MS_CONNECTOR_Library.schlib; Mfr_name: SAMTEC; Mfr_part_number: HSEC8-180 EDGE CONNECTOR; Mistral Part No: NA; Package: SMD; Part_type: CONNECTOR\EDGE; Project: TI_AM263XX_CC; RoHS: NA; Temperature: NA; Tolerance: NA; Voltage: NA; Wattage: NA; Weight: NA; Datasheet: NA
J16-J19 = HEADER_2X1: CON HDR 2X1 2.54MM PITCH ST TH; Chkd/date: VASANTHA/060117; Crtd /date: MAZHAR/280405; Custom_Duty: 24%; Customs_HS_Code: 85369090; Distributor_name: DIGIKEY; Distributor_part_number: WM4000-ND; Footprint Path: Y:\MIS_DATABASE\Library\ALTIUM_TOOL\PCB_FOOTPRINTS\Altium_Footprint_Lib.PcbLib; Height: 10.79MM; Library Path: Y:\MIS_DATABASE\Library\ALTIUM_TOOL\SCHEMATICS_PARTS\MS_CONNECTOR_Library.schlib; Mfr_name: MOLEX; Mfr_part_number: 22-03-2021; Mistral Part No: 150009030246-R; Package: THRU-HOLE; Part_type: CONNECTOR\HEADERS; Project: FPGA EXTENDER CARD; RoHS: RoHS; Temperature: -0°C+75°C; Tolerance: NA; Voltage: NA; Wattage: NA; Weight: 139gm; Datasheet: Y:\MIS_DATABASE\DATASHEETS\CONNECTORS\HEADER_X4030.PDF
R417 = RESISTOR: RES 9.1K 1/16W 1% 0402; Chkd/date: VASANTHA/280616; Crtd /date: VASANTHA/280616; Custom_Duty: 15%; Customs_HS_Code: 85332119; Distributor_name: DIGIKEY; Distributor_part_number: 311-9.10KLRCT-ND; Footprint Path: Y:\MIS_DATABASE\Library\ALTIUM_TOOL\PCB_FOOTPRINTS\Altium_Footprint_Lib.PcbLib; Height: 0.40MM; Library Path: Y:\MIS_DATABASE\Library\ALTIUM_TOOL\SCHEMATICS_PARTS\MS_DISCRETE_Library.schlib; Mfr_name: YAGEO AMERICA; Mfr_part_number: RC0402FR-079K1L; Mistral Part No: 110016060010-R; Package: 0402; Part_type: RESISTORS\FIXED; Project: TMDXCSKCC; RoHS: RoHS; Temperature: -55°C+155°C; Tolerance: 1%; Voltage: NA; Wattage: 1/16W; Weight: 0.65mg; Datasheet: Y:\MIS_DATABASE\DATASHEETS\RESISTORS\RCXXXXL-SER_MAR18.PDF
R418 = RESISTOR: RES 11K 1/16W 1% 0402; Chkd/date: VASANTHA/251115; Crtd /date: VASANTHA/251115; Custom_Duty: 15%; Customs_HS_Code: 85332119; Distributor_name: DIGIKEY; Distributor_part_number: 311-11.0KLRCT-ND; Footprint Path: Y:\MIS_DATABASE\Library\ALTIUM_TOOL\PCB_FOOTPRINTS\Altium_Footprint_Lib.PcbLib; Height: 0.40MM; Library Path: Y:\MIS_DATABASE\Library\ALTIUM_TOOL\SCHEMATICS_PARTS\MS_DISCRETE_Library.schlib; Mfr_name: YAGEO AMERICA; Mfr_part_number: RC0402FR-0711KL; Mistral Part No: 110015110012-R; Package: 0402; Part_type: RESISTORS\FIXED; Project: TI_VLAN_SWITCH; RoHS: RoHS; Temperature: -55°C+155°C; Tolerance: 1%; Voltage: NA; Wattage: 1/16W; Weight: 0.65mg; Datasheet: Y:\MIS_DATABASE\DATASHEETS\RESISTORS\RCXXXXL-SER_MAR18.PDF
U74 U75 = TMUX1136_USON10: IC 5V LOW-LEAKAGE-CURRENT 2:1 2-CHANNEL PRECISION ANALOG SWITCH USON10; Chkd/date: MANIRAJA/291121; Crtd /date: ALVY/291121; Custom_Duty: 15%; Customs_HS_Code: 85423100; Distributor_name: DIGIKEY; Distributor_part_number: 296-TMUX1136DQARCT-ND; Footprint Path: Y:\MIS_DATABASE\Library\ALTIUM_TOOL\PCB_FOOTPRINTS\Altium_Footprint_Lib.PcbLib; Height: 0.55MM; Library Path: Y:\MIS_DATABASE\Library\ALTIUM_TOOL\SCHEMATICS_PARTS\MS_ANALOG-APPLICATION_Library.schlib; Mfr_name: TEXAS INSTRUMENTS; Mistral Part No: 140121110003-R; Package: USON10; Part_type: ICS\ANALOG\SWITCH; Project: TI_AM263x_CC_BRD; RoHS: RoHS; Temperature: -40°C+125°C; Tolerance: NA; Voltage: NA; Wattage: NA; Weight: 4.3mg; Datasheet: Y:\MIS_DATABASE\DATASHEETS\ICS\ANALOG\TMUX1136.PDF

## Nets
DGND: C1.2 C2.2 C3.2 C4.2 C5.2 C6.1 C7.2 C8.2 C9.2 C10.2 C11.2 C12.1 C13.2 C14.2 C15.2 C16.2 C17.2 C18.2 C19.2 C20.2 C22.2 C23.2 C329.2 C330.1 C331.2 C332.2 C333.2 C334.2 C355.2 C376.2 C380.2 D1.2(ANODE) D2.2(ANODE) D3.2(A) J1.A1(GND) J1.A12(GND) J1.B1(GND) J1.B12(GND) J15.7 J15.10 J15.13 J15.16 J15.19 J15.22 J15.29 J15.32 J15.35 J15.38 J15.46 J15.47 J15.65 J15.83 J15.97 J15.111 J15.135 J15.157 J15.179 J16.2 J17.2 J18.2 J19.2 R2.1 R7.2 R8.2 R9.1 R14.2 R15.2 R16.2 R17.2 R18.2 R414.2 R415.2 R416.2 R418.2 R469.1 R551.2 R554.2 U2.3(GND) U3.5(GND) U3.9(EP) U4.9(ST) U4.12(GND) U5.5(GND) U17.10(GND) U74.3(GND) U75.3(GND) ; also on sheet 1 2 3 7 8 9 10 11 12 13 14 15 16 17 24 25 26 27 28 29 30 32 33
VBUS_DET: R5.1 U17.4(VBUS_DET)
VBUS_MAIN: C7.1 R10.1 R11.1 U3.7(VOUT1) U3.8(VOUT2) U4.2(IN2)
VBUS_USBC: C1.1 C2.1 C3.1 C4.1 C5.1 C8.1 D3.1(K) J1.A4(VBUS1) J1.A9(VBUS2) J1.B4(VBUS3) J1.B9(VBUS4) R1.1 R3.1 R4.1 R5.2 R6.1 TP2.1(TP) U2.5(VCC) U3.1(VIN1) U3.2(VIN2) U3.4(VBIAS) U17.12(VDD)
VCC_5V0: J15.117 ; also on sheet 13
VDDA_IO_3V3: C329.1 C330.2 U74.8(VDD) U75.8(VDD) ; also on sheet 2 16
ADC1_MUX_SEL: R414.1 U74.1(SEL1) U74.5(SEL2) ; also on sheet 12
ADC2_MUX_SEL: R415.1 U75.1(SEL1) U75.5(SEL2) ; also on sheet 12
ADC4_AIN0/ADC_CAL0/ADC_R0_AIN0: J15.25 U75.10(D1) ; also on sheet 16
ADC4_AIN1/ADC_CAL1/ADC_R0_AIN1: J15.27 U75.6(D2) ; also on sheet 16
ADC_CAL0/ADC_R0_AIN0: U75.9(S1B) ; also on sheet 2
ADC_CAL1/ADC_R0_AIN1: U75.7(S2B) ; also on sheet 2
BOOST_COMP: C380.1 R552.1 U5.4(COMP)
BOOST_EN: R20.2 R469.2 U5.7(EN)
BOOST_FSW: R550.1 U5.1(FSW)
BOOST_ILIM: R551.1 U5.8(ILIM)
BOOST_SW: C375.2 L7.2 R550.2 U5.11(SW)
C_A5_CC1: D1.1(CATHODE) J1.A5(CC1) U17.1(CC1)
C_B5_CC2: D2.1(CATHODE) J1.B5(CC2) U17.2(CC2)
HSEC_5V0: C13.1 C14.1 C15.1 C332.1 C333.1 C334.1 J15.48 J15.84 J15.98 J15.112 J15.118 J15.158 J15.180 R12.1 R13.1 TP81.1(TP) U4.7(IN1)
HSEC_ADC0_AIN0: U74.2(S1A) ; also on sheet 16
HSEC_ADC0_AIN0/DAC_OUT: J15.9 U74.10(D1) ; also on sheet 16
HSEC_ADC0_AIN1: U74.4(S2A) ; also on sheet 16
HSEC_ADC0_AIN1/DAC_OUT: J15.11 U74.6(D2) ; also on sheet 16
HSEC_ADC0_AIN2: J15.15 ; also on sheet 16
HSEC_ADC0_AIN3: J15.17 ; also on sheet 16
HSEC_ADC0_AIN4: J15.21 ; also on sheet 16
HSEC_ADC0_AIN5: J15.23 ; also on sheet 16
HSEC_ADC1_AIN0: J15.12 ; also on sheet 16
HSEC_ADC1_AIN1: J15.14 ; also on sheet 16
HSEC_ADC1_AIN2: J15.18 ; also on sheet 16
HSEC_ADC1_AIN3: J15.20 ; also on sheet 16
HSEC_ADC1_AIN4: J15.24 ; also on sheet 16
HSEC_ADC1_AIN5: J15.26 ; also on sheet 16
HSEC_ADC2_AIN0/ADC_R1_AIN0: J15.31 ; also on sheet 2
HSEC_ADC2_AIN1/ADC_R1_AIN1: J15.33 ; also on sheet 2
HSEC_ADC2_AIN2: J15.37 ; also on sheet 16
HSEC_ADC2_AIN3: J15.39 ; also on sheet 16
HSEC_ADC3_AIN0/ADC_R0_AIN2: J15.28 ; also on sheet 2
HSEC_ADC3_AIN1/ADC_R0_AIN3: J15.30 ; also on sheet 2
HSEC_ADC3_AIN2/ADC_R1_AIN2: J15.34 ; also on sheet 2
HSEC_ADC3_AIN3/ADC_R1_AIN3: J15.36 ; also on sheet 2
HSEC_ADC3_AIN4: J15.40 ; also on sheet 16
HSEC_ADC3_AIN5: J15.42 ; also on sheet 16
HSEC_ADC4_AIN0: U75.2(S1A) ; also on sheet 16
HSEC_ADC4_AIN1: U75.4(S2A) ; also on sheet 16
HSEC_ADC-VREFHI: C331.1 R417.2 R418.1 ; also on sheet 16
HSEC_DAC_OUT: R412.2 R413.2 ; also on sheet 16
HSEC_EPWM0_A: J15.49 ; also on sheet 27
HSEC_EPWM0_B: J15.51 ; also on sheet 27
HSEC_EPWM1_A: J15.53 ; also on sheet 27
HSEC_EPWM1_B: J15.55 ; also on sheet 27
HSEC_EPWM2_A: J15.50 ; also on sheet 27
HSEC_EPWM2_B: J15.52 ; also on sheet 27
HSEC_EPWM3_A/HSEC_MII1_CRS(RES0_PWMOUT0): J15.54 ; also on sheet 2
HSEC_EPWM3_B: J15.56 ; also on sheet 27
HSEC_EPWM4_A: J15.57 ; also on sheet 27
HSEC_EPWM4_B: J15.59 ; also on sheet 27
HSEC_EPWM5_A: J15.61 ; also on sheet 27
HSEC_EPWM5_B: J15.63 ; also on sheet 27
HSEC_EPWM6_A: J15.58 ; also on sheet 27
HSEC_EPWM6_B: J15.60 ; also on sheet 27
HSEC_EPWM7_A: J15.62 ; also on sheet 27
HSEC_EPWM7_B: J15.64 ; also on sheet 27
HSEC_EPWM11_A: J15.86 ; also on sheet 27
HSEC_EPWM13_A: J15.153 ; also on sheet 27
HSEC_EPWM13_B: J15.154 ; also on sheet 27
HSEC_EPWM21_A: J15.89 ; also on sheet 15
HSEC_EPWM21_B: J15.90 ; also on sheet 15
HSEC_EQEP0_A: J15.102 ; also on sheet 26
HSEC_EQEP0_B: J15.100 ; also on sheet 26
HSEC_EQEP0_INDEX: J15.106 ; also on sheet 26
HSEC_EQEP0_STROBE: J15.104 ; also on sheet 26
HSEC_EQEP2_A: J15.92 ; also on sheet 26
HSEC_EQEP2_B: J15.93 ; also on sheet 26
HSEC_EQEP2_INDEX: J15.94 ; also on sheet 26
HSEC_EQEP2_STROBE: J15.95 ; also on sheet 26
HSEC_EXT_REFCLK0: J15.74 ; also on sheet 27
HSEC_GPIO: J15.96 ; also on sheet 12
HSEC_I2C1_SCL: J15.87 ; also on sheet 26
HSEC_I2C1_SDA: J15.85 ; also on sheet 26
HSEC_MCAN5_RX: J15.80 ; also on sheet 13
HSEC_MCAN5_TX: J15.82 ; also on sheet 13
HSEC_MII0_COL: J15.110 ; also on sheet 32
HSEC_MII0_CRS: J15.121 ; also on sheet 32
HSEC_MII0_RXCLK: J15.123 ; also on sheet 32
HSEC_MII0_RXD0: J15.125 ; also on sheet 32
HSEC_MII0_RXD1: J15.126 ; also on sheet 32
HSEC_MII0_RXD2: J15.127 ; also on sheet 32
HSEC_MII0_RXD3: J15.128 ; also on sheet 32
HSEC_MII0_RXDV: J15.124 ; also on sheet 32
HSEC_MII0_RXER: J15.108 ; also on sheet 32
HSEC_MII0_RXLINK: J15.122 ; also on sheet 32
HSEC_MII0_TXCLK: J15.129 ; also on sheet 32
HSEC_MII0_TXD0: J15.131 ; also on sheet 32
HSEC_MII0_TXD1: J15.132 ; also on sheet 32
HSEC_MII0_TXD2: J15.133 ; also on sheet 32
HSEC_MII0_TXD3: J15.134 ; also on sheet 32
HSEC_MII0_TXEN: J15.130 ; also on sheet 32
HSEC_MII1_COL: J15.138 ; also on sheet 32
HSEC_MII1_CRS(RES0_PWMOUT0): J15.139 ; also on sheet 2 32
HSEC_MII1_RXCLK: J15.141 ; also on sheet 32
HSEC_MII1_RXD0: J15.143 ; also on sheet 32
HSEC_MII1_RXD1: J15.144 ; also on sheet 32
HSEC_MII1_RXD2: J15.145 ; also on sheet 32
HSEC_MII1_RXD3: J15.146 ; also on sheet 32
HSEC_MII1_RXDV: J15.142 ; also on sheet 32
HSEC_MII1_RXER: J15.137 ; also on sheet 32
HSEC_MII1_RXLINK: J15.140 ; also on sheet 32
HSEC_MII1_TXCLK: J15.147 ; also on sheet 32
HSEC_MII1_TXD0: J15.149 ; also on sheet 32
HSEC_MII1_TXD1: J15.150 ; also on sheet 32
HSEC_MII1_TXD2: J15.151 ; also on sheet 32
HSEC_MII1_TXD3: J15.152 ; also on sheet 32
HSEC_MII1_TXEN: J15.148 ; also on sheet 32
HSEC_MMC0_CLK: J15.163 ; also on sheet 25
HSEC_MMC0_CMD: J15.164 ; also on sheet 25
HSEC_MMC0_D0: J15.165 ; also on sheet 25
HSEC_MMC0_D1: J15.166 ; also on sheet 25
HSEC_MMC0_D2: J15.167 ; also on sheet 25
HSEC_MMC0_D3: J15.168 ; also on sheet 25
HSEC_MMC0_SDCD: J15.170 ; also on sheet 25
HSEC_MMC0_WP: J15.169 ; also on sheet 25
HSEC_SDFM0_CLK0: J15.72 ; also on sheet 27
HSEC_SDFM0_CLK1: J15.101 R422.2 ; also on sheet 27
HSEC_SDFM0_CLK2: J15.105 ; also on sheet 27
HSEC_SDFM0_CLK3: J15.109 ; also on sheet 27
HSEC_SDFM0_D0: J15.91 ; also on sheet 27
HSEC_SDFM0_D1: J15.99 R421.2 ; also on sheet 27
HSEC_SDFM0_D2: J15.103 ; also on sheet 27
HSEC_SDFM0_D3: J15.107 ; also on sheet 27
HSEC_SPI0_CLK: J15.71 ; also on sheet 26
HSEC_SPI0_CS0: J15.73 ; also on sheet 26
HSEC_SPI0_D0: J15.67 ; also on sheet 26
HSEC_SPI0_D1: J15.69 ; also on sheet 26
HSEC_SPI1_CLK: J15.79 ; also on sheet 30
HSEC_SPI1_CS0: J15.81 ; also on sheet 30
HSEC_SPI1_D0: J15.75 ; also on sheet 30
HSEC_SPI1_D1: J15.77 ; also on sheet 30
HSEC_TCK: J15.5 ; also on sheet 27
HSEC_TDI: J15.8 ; also on sheet 27
HSEC_TDO: J15.6 ; also on sheet 27
HSEC_TMS: J15.3 ; also on sheet 27
HSEC_UART1_RXD: J15.76 ; also on sheet 9
HSEC_UART1_TXD: J15.78 ; also on sheet 9
HSEC_VREF_3V3: J15.45 R417.1
PMIC_COMP1_IN+: J15.175 ; also on sheet 30
PMIC_COMP1_IN-: J15.177 ; also on sheet 30
PMIC_COMP2_IN+: J15.171 ; also on sheet 30
PMIC_COMP2_IN-: J15.173 ; also on sheet 30
PMIC_SAFE_OUT1: J15.113 ; also on sheet 30
PMIC_SAFE_OUT2: J15.178 ; also on sheet 27 30
PMIC_WKUP1: J15.114 ; also on sheet 30
PMIC_WKUP2: J15.172 ; also on sheet 13 30
PORZ: R419.1 ; also on sheet 7 10 11 15 24 27
PR0_IEP0_EDC_SYNC_OUT0: J16.1 R420.1
PR0_IEP0_EDC_SYNC_OUT1: J18.1 R422.1
PR0_IEP0_EDIO_DATA_IN_OUT30: J17.1 R421.1
PR0_IEP0_EDIO_DATA_IN_OUT31: J19.1 R423.1
PR0_PRU1_GPIO18: J15.70 R423.2 ; also on sheet 7
PR0_PRU1_GPIO19: J15.68 R420.2 ; also on sheet 7
RESETz_HSEC: J15.120 R419.2
TA_POWERDOWNz: R20.1 ; also on sheet 3 28
TPS2121_CP2: R11.2 R15.1 U4.3(CP2)
TPS2121_OV1: R12.2 R16.1 U4.5(OV1)
TPS2121_OV2: R10.2 R14.1 U4.4(OV2)
TPS2121_PR1: R13.2 R17.1 U4.6(PR1)
TPS2296_EN: LD1.1(CATHODE) U2.4(Y) U3.3(ON)
TUSB_OUT1: R4.2 U2.2(B) U17.7(SDA/OUT1)
TUSB_OUT2: R3.2 U2.1(A) U17.8(SCL/OUT2)
UART2_RXD_HSEC: J15.161 ; also on sheet 26
UART2_TXD_HSEC: J15.162 ; also on sheet 26
USBC_EARTH: C6.2 J1.SH1 J1.SH2 J1.SH3 J1.SH4 R9.2
VMAIN: C10.1 C11.1 C12.2 C17.1 C18.1 C19.1 C355.1 L7.1 TP80.1(TP) U4.1(OUT1) U4.8(OUT2) U5.9(VIN) ; also on sheet 1 10 14 26 27 29
VMAIN_12V0: C20.1 C376.1 R553.1 TP79.1(TP) U5.6(VOUT) ; also on sheet 13 30
VSYS_3V3_LDO1: J15.119 ; also on sheet 1 7 9 10 11 12 13 14 15 16 17 24 26 27 28 29 30 32 33
N33461336: J15.43 R416.1
N33933588: R412.1 U74.9(S1B)
N33933633: R413.1 U74.7(S2B)
N35052540: R7.1 U17.5(ADDR)
N35052638: R18.1 U4.10(ILM)
N35052879: C9.1 U3.6(CT)
N35052899: R6.2 U17.6(INT_N/OUT3)
N35052954: R2.2 U17.3(PORT)
N35052969: TP1.1(TP) U17.9(ID)
N35053013: R8.1 U17.11(EN_N)
N35053423: C16.1 U4.11(SS)
N35056553: LD1.2(ANODE) R1.2
N35920046: C23.1 U5.2(VCC)
N35924469: C22.1 R552.2
N35925251: R553.2 R554.1 U5.3(FB)
N35926311: C375.1 U5.10(BOOT)

Not connected (* = marked no-connect by the designer): J1 A2(TX1+) A3(TX1-) A6(D+_1) A7(D-_1) A8(SBU1) A10(RX2-) A11(RX2+) B2(TX2+) B3(TX2-) B6(D+_2) B7(D-_2) B8(SBU2) B10(RX1-) B11(RX1+); J15 1* 2* 4* 41* 44* 66* 88* 115* 116* 136* 155* 156* 159* 160* 174* 176*

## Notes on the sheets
sheet 4
- USB-C Power
- Configured as UFP MODE
  To Detect 5V/3A Source
- USB- C Connector
- RED
- POWER ERROR
  INDICATION LED
- Power MUX
- XCOMP
- OUTPUT
- OV2 set to 0.877V
- CP2 set to 1.65V
- OV1 set to 0.877V
- PR1 set to 2.5V
- PR1 > CP2
- HSEC_5V0
- PR1 = < CP2
- VBUS_MAIN
- OVP Set to 6.08V
- 3A max Output
- Designed as per reference sch
- BOOST CONVERTER - 12V0
- TA_POWERDOWNz pulled to VSYS_TA_3V3
sheet 5
- POWER SEQUENCE
sheet 6
- HSEC Connector
- 3.3V to 1.8V
  divider
- SYNC TP
- SILK:
- SYNC0
- SILK:
- DIO30
- SILK:
- SYNC1
- SILK:
- DIO31
- CAD NOTE: Place the
  resistors close to SOC
  to minimize the stub
